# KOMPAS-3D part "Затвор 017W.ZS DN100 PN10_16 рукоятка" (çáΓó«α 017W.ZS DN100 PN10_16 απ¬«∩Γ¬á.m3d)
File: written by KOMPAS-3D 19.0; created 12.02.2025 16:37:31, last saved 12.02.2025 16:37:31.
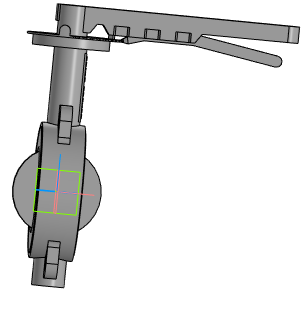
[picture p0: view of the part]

Document properties: Автор: Евгений; Полное имя файла: Затвор 017W.ZS DN100 PN10_16 рукоятка.a3d

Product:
- Part/product: Затвор 017W.ZS DN100 PN10_16 рукоятка
    Масса: 15.9682

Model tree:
1. Операция без истории:1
